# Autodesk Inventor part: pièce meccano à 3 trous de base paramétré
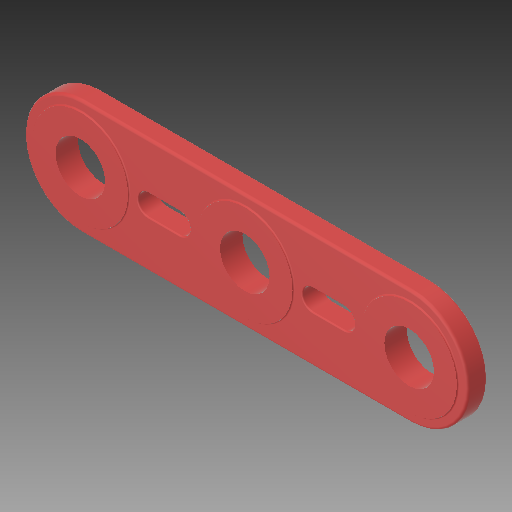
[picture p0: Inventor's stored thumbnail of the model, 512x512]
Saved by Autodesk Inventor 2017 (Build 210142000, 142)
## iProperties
Part Number: pièce meccano à 3 trous de base paramétré
Material: Plastique PC/ABS
Document SubType Name: Modeling
Designer: ficho
Density: 0.357273 g/cm^3
Appearance: Lisse - Rouge
Mass: 2.10648 g
Surface Area: 42.2884 cm^2
Volume: 5.89601 cm^3
Author: ficho
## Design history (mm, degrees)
sketch "Esquisse1"
  geometry: L1 (63, 11)-(0, 11); L2 (63, -11)-(0, -11); A1 r 11 centre (0, 0) between (0, 11) and (0, -11); A2 r 11 centre (63, 0) between (63, -11) and (63, 11); 1 further point
  constraints: 4 end point, 4 point on circle, 4 tangent, 2 centre point, 1 coincident
  dimensions: "d0" = 22 diameter of A1 (= largeur); "d1" = 22 diameter of A2 (= largeur); "d2" = 85 dimension on A2 A1 (= long)
extrude "Extrusion1" new body sketch "Esquisse1" distance "d3" = 3.8 (= ep); taper "d4" = 0 deg
fillet "Congé1" dims "d5" = 0.5
fillet "Congé2" dims "d6" = 0.5
sketch "Esquisse2"
  geometry: C1 r 9.15 at (0, 0); 1 further point
  constraints: 1 centre point, 1 coincident
  dimensions: "d14" = 18.3 diameter of C1
extrude "Extrusion2" join sketch "Esquisse2" distance "d15" = 0.25; taper "d16" = 0 deg
node "Plan de construction1"
mirror "Symétrie1"
fillet "Congé4" dims "d19" = 0.25
sketch "Esquisse4"
  geometry: 1 further point
hole "Perçage2" sketch "Esquisse4" at (0, 0) diameter "d20" = 9.5 (= alesage); stored, may be unused: countersink angle "d24" = 90 deg, drill point angle "d26" = 118 deg; dims "d21" = 6, "d22" = 4, "d23" = 2, "d25" = 8
pattern_linear "Réseau rectangulaire1" dims "d29" = 31.5 (= repet)
sketch "Esquisse5"
  geometry: L1 (18.75, 2)-(12.75, 2); L2 (18.75, -2)-(12.75, -2); C1 r 4.75 at (31.5, 0) reference; A1 r 2 centre (18.75, 0) between (18.75, -2) and (18.75, 2); A2 r 2 centre (12.75, 0) between (12.75, 2) and (12.75, -2); 1 further point
  constraints: 4 end point, 4 point on circle, 4 tangent, 2 centre point
  dimensions: "d30" = 4 diameter of A1; "d31" = 4 diameter of A2; "d32" = 6 distance of A2.centre A1.centre; "d33" = 12.75 distance of A2.centre point (0, 0)
extrude "Extrusion3" cut sketch "Esquisse5" stored distance "d35" = 0.25; taper "d36" = 0 deg
fillet "Congé5" dims "d37" = 0.25
pattern_linear "Réseau rectangulaire2" dims "d40" = 31.5 (= repet)
node "Solide1"
other parameters: "largeur" = 22 [user parameter; used in 2 equation terms], "long" = 85 [user parameter; used in 1 equation term], "ep" = 3.8 [user parameter; used in 2 equation terms], "alesage" = 9.5 [user parameter; used in 1 equation term], "d18" = -1.9 (= -0.5 x ep), "repet" = 31.5 [user parameter; used in 2 equation terms]
